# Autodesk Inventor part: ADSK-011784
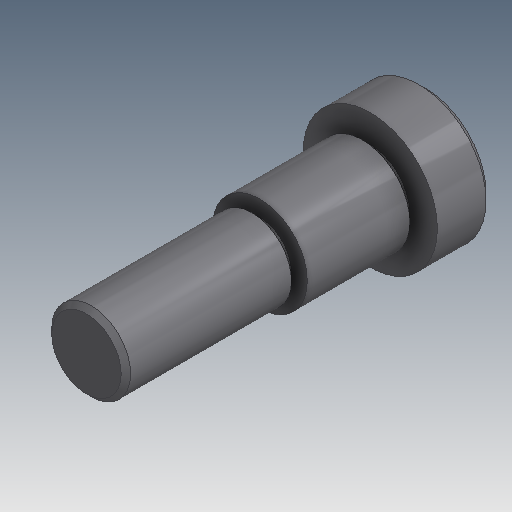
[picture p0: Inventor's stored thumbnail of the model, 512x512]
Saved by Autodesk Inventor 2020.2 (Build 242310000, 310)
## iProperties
Created: 1999-11
Part Number: ADSK-011784
Material: Acier doux
Document SubType Name: Modeling
Designer: mpflueger
Density: 7.86 g/cm^3
Appearance: Metal-Steel(Polish)
Mass: 37.3471 g
Surface Area: 21.7375 cm^2
Volume: 4.75154 cm^3
Control State: 0
Master: False
Checked Out: False
Shininess: 0.0
Length Units: 11272
Angle Units: 11279
Time Units: 11290
Mass Units: 11286
Length Display Precision: 3
Angle Display Precision: 2
Compacted: True
Dimensions: 0,7x1,7x0,7 in
Mass: 0,082 lb
VLT_Material: Acier doux
Density: 0.0
Volumn: 0.0
Area: 0.0
PropertySet Name: Model Information
Author: mpflueger
Revision Number: -
Title: ADSK-011784
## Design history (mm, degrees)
node "Extrusion1" dims "d1" = 7, "d2" = 0
node "Extrusion2" dims "d4" = 1, "d5" = 0
node "Extrusion3" dims "d7" = 13, "d8" = 0
node "Extrusion4" dims "d10" = 1, "d11" = 0
node "Extrusion5" dims "d13" = 21, "d14" = 0
node "Chamfer1" dims "d15" = 0.59944, "d16" = 0.59944, "d21" = 45 deg
node "Chamfer2" dims "d17" = 0.83344, "d18" = 0.83344, "d22" = 45 deg
node "Hexagon_flats_cut1"
node "Solide1"
node "Corps solides"
node "Corps surfaciques"
sketch "Sketch1"
  geometry: C1 r 8.5 at (0, 0)
  constraints: 1 centre point, 1 other
  dimensions: "d0" = 17 diameter of C1
sketch "Sketch2"
  geometry: C1 r 8.5 at (0, 0) reference; C2 r 5 at (0, 0)
  constraints: 1 centre point, 1 coincident
  dimensions: "d3" = 10 diameter of C2
sketch "Sketch3"
  geometry: C1 r 5 at (0, 0) reference; C2 r 6 at (0, 0)
  constraints: 1 centre point, 1 coincident
  dimensions: "d6" = 12 diameter of C2
sketch "Sketch4"
  geometry: C1 r 6 at (0, 0) reference; C2 r 4 at (0, 0)
  constraints: 1 centre point, 1 coincident
  dimensions: "d9" = 8 diameter of C2
sketch "Sketch5"
  geometry: C1 r 4 at (0, 0) reference; C2 r 5 at (0, 0)
  constraints: 1 centre point, 1 coincident
  dimensions: "d12" = 10 diameter of C2
sketch "Sketch6"
  geometry: L1 (-1.215, 2.553)-(0.529, 4.678); L2 (0.529, 4.678)-(3.242, 4.23); L3 (3.242, 4.23)-(4.211, 1.657); L4 (4.211, 1.657)-(2.466, -0.469); L5 (2.466, -0.469)-(-0.247, -0.021); L6 (-0.247, -0.021)-(-1.215, 2.553); C1 r 2.381 at (1.498, 2.105)
  constraints: 12 end point, 5 tangent, 3 equal length, 3 parallel, 1 centre point
  dimensions: "d19" = 4.7625 diameter of C1 (derived)
